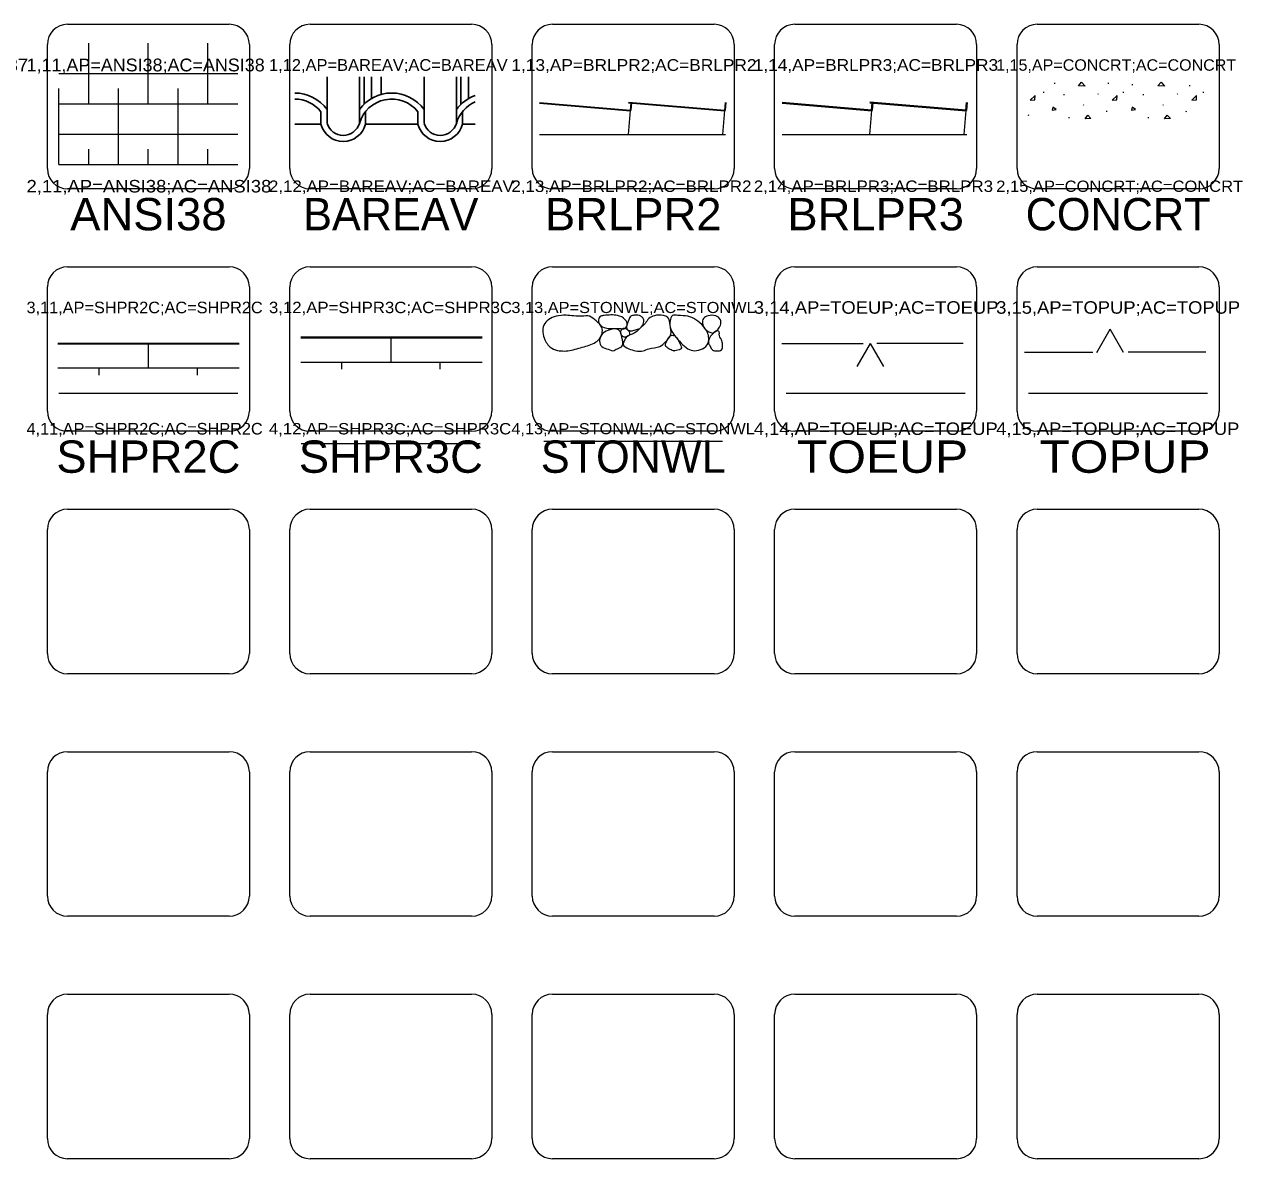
# Model space of a CAD drawing. Extents: x 95935 to 95946.4, y 95971.2 to 95974.7.
# Drawn here: x 95941.029 to 95944.034, y 95971.925 to 95974.732 of the extents above; entities that cross this region are included whole.
import ezdxf
from ezdxf.enums import TextEntityAlignment as Align

# ---------------------------------------------------------------- set-up
doc = ezdxf.new("R2010")
doc.units = 0
doc.header["$LTSCALE"] = 0.032
for name, color, linetype, lineweight in [('1', 7, 'Continuous', 13), ('25', 7, 'Continuous', 13), ('6', 7, 'Continuous', 13), ('63', 7, 'Continuous', 13)]:
    doc.layers.add(name, color=color, linetype=linetype, lineweight=lineweight)
doc.layers.add('20', color=7, linetype='Continuous')

msp = doc.modelspace()

# ---------------------------------------------------------------- linework, layer by layer
at = {"layer": '1'}
for p, q in [((95941.1357, 95974.7318), (95941.5357, 95974.7318)), ((95941.7357, 95974.7318), (95942.1357, 95974.7318)), ((95942.3357, 95974.7318), (95942.7357, 95974.7318)), ((95942.9357, 95974.7318), (95943.3357, 95974.7318)), ((95943.5357, 95974.7318), (95943.9357, 95974.7318)), ((95941.0857, 95974.3747), (95941.0857, 95974.6818)), ((95941.5857, 95974.6818), (95941.5857, 95974.3747)), ((95941.6857, 95974.3747), (95941.6857, 95974.6818)), ((95942.1857, 95974.6818), (95942.1857, 95974.3747)), ((95942.2857, 95974.3747), (95942.2857, 95974.6818)), ((95942.7857, 95974.6818), (95942.7857, 95974.3747)), ((95942.8857, 95974.3747), (95942.8857, 95974.6818)), ((95943.3857, 95974.6818), (95943.3857, 95974.3747)), ((95943.4857, 95974.3747), (95943.4857, 95974.6818)), ((95943.9857, 95974.6818), (95943.9857, 95974.3747)), ((95941.5357, 95974.3247), (95941.1357, 95974.3247)), ((95942.1357, 95974.3247), (95941.7357, 95974.3247)), ((95942.7357, 95974.3247), (95942.3357, 95974.3247)), ((95943.3357, 95974.3247), (95942.9357, 95974.3247)), ((95943.9357, 95974.3247), (95943.5357, 95974.3247)), ((95941.1357, 95974.1318), (95941.5357, 95974.1318)), ((95941.7357, 95974.1318), (95942.1357, 95974.1318)), ((95942.3357, 95974.1318), (95942.7357, 95974.1318)), ((95942.9357, 95974.1318), (95943.3357, 95974.1318)), ((95943.5357, 95974.1318), (95943.9357, 95974.1318)), ((95941.0857, 95973.7747), (95941.0857, 95974.0818)), ((95941.5857, 95974.0818), (95941.5857, 95973.7747)), ((95941.6857, 95973.7747), (95941.6857, 95974.0818)), ((95942.1857, 95974.0818), (95942.1857, 95973.7747)), ((95942.2857, 95973.7747), (95942.2857, 95974.0818)), ((95942.7857, 95974.0818), (95942.7857, 95973.7747)), ((95942.8857, 95973.7747), (95942.8857, 95974.0818)), ((95943.3857, 95974.0818), (95943.3857, 95973.7747)), ((95943.4857, 95973.7747), (95943.4857, 95974.0818)), ((95943.9857, 95974.0818), (95943.9857, 95973.7747)), ((95941.5357, 95973.7247), (95941.1357, 95973.7247)), ((95942.1357, 95973.7247), (95941.7357, 95973.7247)), ((95942.7357, 95973.7247), (95942.3357, 95973.7247)), ((95943.3357, 95973.7247), (95942.9357, 95973.7247)), ((95943.9357, 95973.7247), (95943.5357, 95973.7247)), ((95941.1357, 95973.5318), (95941.5357, 95973.5318)), ((95941.7357, 95973.5318), (95942.1357, 95973.5318)), ((95942.3357, 95973.5318), (95942.7357, 95973.5318)), ((95942.9357, 95973.5318), (95943.3357, 95973.5318)), ((95943.5357, 95973.5318), (95943.9357, 95973.5318)), ((95941.0857, 95973.1747), (95941.0857, 95973.4818)), ((95941.5857, 95973.4818), (95941.5857, 95973.1747)), ((95941.6857, 95973.1747), (95941.6857, 95973.4818)), ((95942.1857, 95973.4818), (95942.1857, 95973.1747)), ((95942.2857, 95973.1747), (95942.2857, 95973.4818)), ((95942.7857, 95973.4818), (95942.7857, 95973.1747)), ((95942.8857, 95973.1747), (95942.8857, 95973.4818)), ((95943.3857, 95973.4818), (95943.3857, 95973.1747)), ((95943.4857, 95973.1747), (95943.4857, 95973.4818)), ((95943.9857, 95973.4818), (95943.9857, 95973.1747)), ((95941.5357, 95973.1247), (95941.1357, 95973.1247)), ((95942.1357, 95973.1247), (95941.7357, 95973.1247)), ((95942.7357, 95973.1247), (95942.3357, 95973.1247)), ((95943.3357, 95973.1247), (95942.9357, 95973.1247)), ((95943.9357, 95973.1247), (95943.5357, 95973.1247)), ((95941.1357, 95972.9318), (95941.5357, 95972.9318)), ((95941.7357, 95972.9318), (95942.1357, 95972.9318)), ((95942.3357, 95972.9318), (95942.7357, 95972.9318)), ((95942.9357, 95972.9318), (95943.3357, 95972.9318)), ((95943.5357, 95972.9318), (95943.9357, 95972.9318)), ((95941.0857, 95972.5747), (95941.0857, 95972.8818)), ((95941.5857, 95972.8818), (95941.5857, 95972.5747)), ((95941.6857, 95972.5747), (95941.6857, 95972.8818)), ((95942.1857, 95972.8818), (95942.1857, 95972.5747)), ((95942.2857, 95972.5747), (95942.2857, 95972.8818)), ((95942.7857, 95972.8818), (95942.7857, 95972.5747)), ((95942.8857, 95972.5747), (95942.8857, 95972.8818)), ((95943.3857, 95972.8818), (95943.3857, 95972.5747)), ((95943.4857, 95972.5747), (95943.4857, 95972.8818)), ((95943.9857, 95972.8818), (95943.9857, 95972.5747)), ((95941.5357, 95972.5247), (95941.1357, 95972.5247)), ((95942.1357, 95972.5247), (95941.7357, 95972.5247)), ((95942.7357, 95972.5247), (95942.3357, 95972.5247)), ((95943.3357, 95972.5247), (95942.9357, 95972.5247)), ((95943.9357, 95972.5247), (95943.5357, 95972.5247)), ((95941.1357, 95972.3318), (95941.5357, 95972.3318)), ((95941.7357, 95972.3318), (95942.1357, 95972.3318)), ((95942.3357, 95972.3318), (95942.7357, 95972.3318)), ((95942.9357, 95972.3318), (95943.3357, 95972.3318)), ((95943.5357, 95972.3318), (95943.9357, 95972.3318)), ((95941.0857, 95971.9747), (95941.0857, 95972.2818)), ((95941.5857, 95972.2818), (95941.5857, 95971.9747)), ((95941.6857, 95971.9747), (95941.6857, 95972.2818)), ((95942.1857, 95972.2818), (95942.1857, 95971.9747)), ((95942.2857, 95971.9747), (95942.2857, 95972.2818)), ((95942.7857, 95972.2818), (95942.7857, 95971.9747)), ((95942.8857, 95971.9747), (95942.8857, 95972.2818)), ((95943.3857, 95972.2818), (95943.3857, 95971.9747)), ((95943.4857, 95971.9747), (95943.4857, 95972.2818)), ((95943.9857, 95972.2818), (95943.9857, 95971.9747)), ((95941.5357, 95971.9247), (95941.1357, 95971.9247)), ((95942.1357, 95971.9247), (95941.7357, 95971.9247)), ((95942.7357, 95971.9247), (95942.3357, 95971.9247)), ((95943.3357, 95971.9247), (95942.9357, 95971.9247)), ((95943.9357, 95971.9247), (95943.5357, 95971.9247))]:
    msp.add_line(p, q, dxfattribs=at)
for centre, start, end in [((95941.1357, 95974.6818), 90, 180), ((95941.5357, 95974.6818), 0, 90), ((95941.7357, 95974.6818), 90, 180), ((95942.1357, 95974.6818), 0, 90), ((95942.3357, 95974.6818), 90, 180), ((95942.7357, 95974.6818), 0, 90), ((95942.9357, 95974.6818), 90, 180), ((95943.3357, 95974.6818), 0, 90), ((95943.5357, 95974.6818), 90, 180), ((95943.9357, 95974.6818), 0, 90), ((95941.1357, 95974.3747), 180, 270), ((95941.5357, 95974.3747), 270, 0), ((95941.7357, 95974.3747), 180, 270), ((95942.1357, 95974.3747), 270, 0), ((95942.3357, 95974.3747), 180, 270), ((95942.7357, 95974.3747), 270, 0), ((95942.9357, 95974.3747), 180, 270), ((95943.3357, 95974.3747), 270, 0), ((95943.5357, 95974.3747), 180, 270), ((95943.9357, 95974.3747), 270, 0), ((95941.1357, 95974.0818), 90, 180), ((95941.5357, 95974.0818), 0, 90), ((95941.7357, 95974.0818), 90, 180), ((95942.1357, 95974.0818), 0, 90), ((95942.3357, 95974.0818), 90, 180), ((95942.7357, 95974.0818), 0, 90), ((95942.9357, 95974.0818), 90, 180), ((95943.3357, 95974.0818), 0, 90), ((95943.5357, 95974.0818), 90, 180), ((95943.9357, 95974.0818), 0, 90), ((95941.1357, 95973.7747), 180, 270), ((95941.5357, 95973.7747), 270, 0), ((95941.7357, 95973.7747), 180, 270), ((95942.1357, 95973.7747), 270, 0), ((95942.3357, 95973.7747), 180, 270), ((95942.7357, 95973.7747), 270, 0), ((95942.9357, 95973.7747), 180, 270), ((95943.3357, 95973.7747), 270, 0), ((95943.5357, 95973.7747), 180, 270), ((95943.9357, 95973.7747), 270, 0), ((95941.1357, 95973.4818), 90, 180), ((95941.5357, 95973.4818), 0, 90), ((95941.7357, 95973.4818), 90, 180), ((95942.1357, 95973.4818), 0, 90), ((95942.3357, 95973.4818), 90, 180), ((95942.7357, 95973.4818), 0, 90), ((95942.9357, 95973.4818), 90, 180), ((95943.3357, 95973.4818), 0, 90), ((95943.5357, 95973.4818), 90, 180), ((95943.9357, 95973.4818), 0, 90), ((95941.1357, 95973.1747), 180, 270), ((95941.5357, 95973.1747), 270, 0), ((95941.7357, 95973.1747), 180, 270), ((95942.1357, 95973.1747), 270, 0), ((95942.3357, 95973.1747), 180, 270), ((95942.7357, 95973.1747), 270, 0), ((95942.9357, 95973.1747), 180, 270), ((95943.3357, 95973.1747), 270, 0), ((95943.5357, 95973.1747), 180, 270), ((95943.9357, 95973.1747), 270, 0), ((95941.1357, 95972.8818), 90, 180), ((95941.5357, 95972.8818), 0, 90), ((95941.7357, 95972.8818), 90, 180), ((95942.1357, 95972.8818), 0, 90), ((95942.3357, 95972.8818), 90, 180), ((95942.7357, 95972.8818), 0, 90), ((95942.9357, 95972.8818), 90, 180), ((95943.3357, 95972.8818), 0, 90), ((95943.5357, 95972.8818), 90, 180), ((95943.9357, 95972.8818), 0, 90), ((95941.1357, 95972.5747), 180, 270), ((95941.5357, 95972.5747), 270, 0), ((95941.7357, 95972.5747), 180, 270), ((95942.1357, 95972.5747), 270, 0), ((95942.3357, 95972.5747), 180, 270), ((95942.7357, 95972.5747), 270, 0), ((95942.9357, 95972.5747), 180, 270), ((95943.3357, 95972.5747), 270, 0), ((95943.5357, 95972.5747), 180, 270), ((95943.9357, 95972.5747), 270, 0), ((95941.1357, 95972.2818), 90, 180), ((95941.5357, 95972.2818), 0, 90), ((95941.7357, 95972.2818), 90, 180), ((95942.1357, 95972.2818), 0, 90), ((95942.3357, 95972.2818), 90, 180), ((95942.7357, 95972.2818), 0, 90), ((95942.9357, 95972.2818), 90, 180), ((95943.3357, 95972.2818), 0, 90), ((95943.5357, 95972.2818), 90, 180), ((95943.9357, 95972.2818), 0, 90), ((95941.1357, 95971.9747), 180, 270), ((95941.5357, 95971.9747), 270, 0), ((95941.7357, 95971.9747), 180, 270), ((95942.1357, 95971.9747), 270, 0), ((95942.3357, 95971.9747), 180, 270), ((95942.7357, 95971.9747), 270, 0), ((95942.9357, 95971.9747), 180, 270), ((95943.3357, 95971.9747), 270, 0), ((95943.5357, 95971.9747), 180, 270), ((95943.9357, 95971.9747), 270, 0)]:
    msp.add_arc(centre, 0.05, start, end, dxfattribs=at)
at = {"layer": '25'}
for p, q in [((95941.5569, 95973.8178), (95941.1141, 95973.8178)), ((95943.3569, 95973.8178), (95942.9141, 95973.8178)), ((95943.9569, 95973.8178), (95943.5141, 95973.8178)), ((95942.1569, 95973.6934), (95941.7141, 95973.6934)), ((95942.7569, 95973.6996), (95942.3141, 95973.6996))]:
    msp.add_line(p, q, dxfattribs=at)
at = {"layer": '6'}
for p, q in [((95941.1879, 95974.5352), (95941.1879, 95974.6852)), ((95941.3355, 95974.5352), (95941.3355, 95974.6852)), ((95941.4831, 95974.5352), (95941.4831, 95974.6852)), ((95941.1141, 95974.6102), (95941.5569, 95974.6102)), ((95941.1141, 95974.3852), (95941.1141, 95974.5727)), ((95941.2617, 95974.3852), (95941.2617, 95974.5727)), ((95941.4093, 95974.3852), (95941.4093, 95974.5727)), ((95943.5521, 95974.562), (95943.5521, 95974.5643)), ((95943.579, 95974.5847), (95943.579, 95974.5872)), ((95943.7122, 95974.5847), (95943.7122, 95974.5872)), ((95943.7488, 95974.562), (95943.7488, 95974.5643)), ((95943.7714, 95974.581), (95943.7714, 95974.5834)), ((95943.9137, 95974.5789), (95943.9137, 95974.5814)), ((95943.9468, 95974.562), (95943.9468, 95974.5643)), ((95941.1141, 95974.5352), (95941.5569, 95974.5352)), ((95943.6021, 95974.5565), (95943.6021, 95974.559)), ((95943.687, 95974.5583), (95943.6863, 95974.56)), ((95943.7987, 95974.5565), (95943.7987, 95974.559)), ((95943.8836, 95974.5583), (95943.8828, 95974.56)), ((95942.5242, 95974.4591), (95942.5291, 95974.5187)), ((95942.7576, 95974.4591), (95942.7625, 95974.5187)), ((95943.1214, 95974.4591), (95943.1263, 95974.5187)), ((95943.3548, 95974.4591), (95943.3597, 95974.5187)), ((95943.5141, 95974.5062), (95943.5147, 95974.5087)), ((95943.6502, 95974.5316), (95943.6512, 95974.5336)), ((95943.7077, 95974.5149), (95943.7082, 95974.5175)), ((95943.8469, 95974.5316), (95943.8478, 95974.5336)), ((95943.9044, 95974.5149), (95943.9047, 95974.5175)), ((95943.6143, 95974.4998), (95943.6145, 95974.5018)), ((95943.811, 95974.4998), (95943.811, 95974.5018)), ((95941.1141, 95974.4602), (95941.5569, 95974.4602)), ((95942.3034, 95974.4591), (95942.5308, 95974.4591)), ((95942.5242, 95974.4591), (95942.7642, 95974.4591)), ((95942.9042, 95974.4591), (95943.128, 95974.4591)), ((95943.1214, 95974.4591), (95943.3614, 95974.4591)), ((95941.1879, 95974.3852), (95941.1879, 95974.4227)), ((95941.3355, 95974.3852), (95941.3355, 95974.4227)), ((95941.4831, 95974.3852), (95941.4831, 95974.4227)), ((95941.1141, 95974.3852), (95941.5569, 95974.3852)), ((95943.6833, 95973.92), (95943.7161, 95973.977)), ((95943.749, 95973.92), (95943.7161, 95973.977)), ((95941.3348, 95973.9421), (95941.3348, 95973.8814)), ((95941.3348, 95973.9421), (95941.3348, 95973.8814)), ((95941.9355, 95973.9565), (95941.9355, 95973.8958)), ((95941.9355, 95973.9565), (95941.9355, 95973.8958)), ((95942.9034, 95973.9418), (95943.1049, 95973.9418)), ((95943.0899, 95973.8849), (95943.1227, 95973.9418)), ((95943.1556, 95973.8849), (95943.1227, 95973.9418)), ((95943.3521, 95973.9418), (95943.1383, 95973.9418)), ((95943.5041, 95973.9201), (95943.6734, 95973.9201)), ((95943.9528, 95973.9201), (95943.7606, 95973.9201)), ((95941.1118, 95973.8814), (95941.3348, 95973.8814)), ((95941.2133, 95973.8814), (95941.2133, 95973.8639)), ((95941.3348, 95973.8814), (95941.5605, 95973.8814)), ((95941.4563, 95973.8814), (95941.4563, 95973.8639)), ((95941.7127, 95973.8958), (95941.9355, 95973.8958)), ((95941.814, 95973.8958), (95941.814, 95973.8783)), ((95941.9355, 95973.8958), (95942.1614, 95973.8958)), ((95942.057, 95973.8958), (95942.057, 95973.8783))]:
    msp.add_line(p, q, dxfattribs=at)
at = {"layer": '6', "lineweight": 25}
for p, q in [((95941.7779, 95974.4868), (95941.7779, 95974.6018)), ((95941.8579, 95974.4868), (95941.8579, 95974.6018)), ((95941.8694, 95974.534), (95941.8694, 95974.6018)), ((95941.8879, 95974.5481), (95941.8879, 95974.6018)), ((95941.9115, 95974.5582), (95941.9115, 95974.6018)), ((95942.0179, 95974.4868), (95942.0179, 95974.6018)), ((95942.0979, 95974.4868), (95942.0979, 95974.6018)), ((95942.1094, 95974.534), (95942.1094, 95974.6018)), ((95942.1279, 95974.5481), (95942.1279, 95974.6018)), ((95941.7629, 95974.4848), (95941.7629, 95974.5156)), ((95941.8729, 95974.4848), (95941.8729, 95974.5156)), ((95942.0029, 95974.4848), (95942.0029, 95974.5156)), ((95942.1129, 95974.4848), (95942.1129, 95974.5156)), ((95941.7629, 95974.4848), (95941.6979, 95974.4848)), ((95942.0029, 95974.4848), (95941.8729, 95974.4848)), ((95942.1448, 95974.4848), (95942.1129, 95974.4848))]:
    msp.add_line(p, q, dxfattribs=at)
at = {"layer": '6', "lineweight": 35}
for p, q in [((95942.3034, 95974.5375), (95942.5291, 95974.5187)), ((95942.5242, 95974.5385), (95942.7625, 95974.5187)), ((95942.5308, 95974.5385), (95942.5291, 95974.5187)), ((95942.7642, 95974.5385), (95942.7625, 95974.5187)), ((95941.1118, 95973.9421), (95941.3348, 95973.9421)), ((95941.3348, 95973.9421), (95941.5605, 95973.9421))]:
    msp.add_line(p, q, dxfattribs=at)
at = {"layer": '6', "lineweight": 40}
for p, q in [((95942.9042, 95974.5372), (95943.1263, 95974.5187)), ((95943.1214, 95974.5385), (95943.3597, 95974.5187)), ((95943.128, 95974.5385), (95943.1263, 95974.5187)), ((95943.3614, 95974.5385), (95943.3597, 95974.5187)), ((95941.7127, 95973.9565), (95941.9355, 95973.9565)), ((95941.9355, 95973.9565), (95942.1614, 95973.9565))]:
    msp.add_line(p, q, dxfattribs=at)
at = {"layer": '6'}
for points in [[(95943.6377, 95974.5798), (95943.6454, 95974.5882), (95943.6542, 95974.5788)], [(95943.8342, 95974.5798), (95943.8422, 95974.5882), (95943.8507, 95974.5788)], [(95943.5295, 95974.5446), (95943.5301, 95974.5558), (95943.5179, 95974.5439)], [(95943.7328, 95974.5446), (95943.7336, 95974.5558), (95943.7214, 95974.5439)], [(95943.9296, 95974.5446), (95943.9301, 95974.5558), (95943.918, 95974.5439)], [(95943.5727, 95974.5195), (95943.5827, 95974.5207), (95943.5742, 95974.5264)], [(95943.6544, 95974.4981), (95943.6609, 95974.507), (95943.6686, 95974.4985)], [(95943.7693, 95974.5195), (95943.7792, 95974.5207), (95943.7707, 95974.5264)], [(95943.8509, 95974.4981), (95943.8576, 95974.507), (95943.8652, 95974.4985)]]:
    msp.add_lwpolyline(points, close=True, dxfattribs=at)
at = {"layer": '6', "lineweight": 25}
for centre, radius, start, end in [((95941.6979, 95974.4634), 0.0983, 35.5548, 90), ((95941.6979, 95974.4634), 0.0833, 38.7394, 90), ((95941.9379, 95974.4634), 0.0983, 35.5548, 144.4452), ((95941.9379, 95974.4634), 0.0833, 38.7394, 163.7398), ((95942.1779, 95974.4634), 0.0983, 109.6705, 144.4452), ((95942.1779, 95974.4634), 0.0833, 113.4032, 163.7398), ((95941.8179, 95974.4984), 0.0567, 193.9306, 346.0694), ((95941.8179, 95974.4984), 0.0417, 196.2602, 343.7398), ((95942.0579, 95974.4984), 0.0567, 193.9306, 346.0694), ((95942.0579, 95974.4984), 0.0417, 196.2602, 343.7398)]:
    msp.add_arc(centre, radius, start, end, dxfattribs=at)
at = {"layer": '6'}
for points in [[(95942.3527, 95973.9238), (95942.3345, 95973.9301), (95942.317, 95973.9511), (95942.3144, 95973.9874), (95942.3446, 95974.0093), (95942.3693, 95974.0119), (95942.4082, 95974.0093), (95942.4275, 95974.0093), (95942.4441, 95973.998), (95942.458, 95973.9814), (95942.4519, 95973.9532), (95942.4387, 95973.9428), (95942.4053, 95973.9316), (95942.3693, 95973.9235), (95942.3527, 95973.9238)], [(95942.4775, 95973.9788), (95942.4634, 95973.9814), (95942.4513, 95973.9909), (95942.4496, 95974.0009), (95942.4554, 95974.0093), (95942.4637, 95974.0113), (95942.4965, 95974.0113), (95942.5161, 95974.0009), (95942.5204, 95973.9877), (95942.5144, 95973.9791), (95942.5051, 95973.9788), (95942.4775, 95973.9788)], [(95942.5411, 95973.9235), (95942.5244, 95973.929), (95942.5106, 95973.9399), (95942.5132, 95973.9483), (95942.5192, 95973.9583), (95942.5382, 95973.9675), (95942.552, 95973.9788), (95942.5659, 95973.9926), (95942.5742, 95974.0035), (95942.5883, 95974.0107), (95942.6102, 95974.011), (95942.6214, 95974.0064), (95942.6269, 95973.9871), (95942.6289, 95973.9652), (95942.6153, 95973.9457), (95942.6018, 95973.9345), (95942.5742, 95973.929), (95942.5604, 95973.9235), (95942.5411, 95973.9235)], [(95942.552, 95973.9788), (95942.5411, 95973.9759), (95942.5299, 95973.9733), (95942.5215, 95973.9759), (95942.519, 95973.9814), (95942.5215, 95973.9926), (95942.5244, 95974.0009), (95942.5299, 95974.0093), (95942.5382, 95974.0119), (95942.5549, 95974.0093), (95942.5604, 95974.0035), (95942.5604, 95973.9897), (95942.552, 95973.9788)], [(95942.6876, 95973.9235), (95942.6712, 95973.929), (95942.6545, 95973.9428), (95942.6378, 95973.9621), (95942.6271, 95973.9825), (95942.6269, 95973.998), (95942.6329, 95974.011), (95942.6464, 95974.0116), (95942.6712, 95974.0093), (95942.6904, 95974.0009), (95942.7097, 95973.9842), (95942.7224, 95973.9592), (95942.7209, 95973.9428), (95942.7071, 95973.929), (95942.6876, 95973.9235)], [(95942.7319, 95973.9675), (95942.7152, 95973.9759), (95942.7071, 95973.9926), (95942.7097, 95974.0035), (95942.7212, 95974.0104), (95942.7399, 95974.0104), (95942.7514, 95974.0009), (95942.7514, 95973.9874), (95942.7373, 95973.9704), (95942.7319, 95973.9675)], [(95942.4856, 95973.9235), (95942.4692, 95973.929), (95942.4554, 95973.9373), (95942.4525, 95973.9511), (95942.4608, 95973.9675), (95942.4778, 95973.9759), (95942.4994, 95973.9756), (95942.5077, 95973.9566), (95942.5086, 95973.9359), (95942.4968, 95973.929), (95942.4856, 95973.9235)], [(95942.5192, 95973.9583), (95942.5106, 95973.9595), (95942.5051, 95973.965), (95942.5051, 95973.9733), (95942.5106, 95973.9788), (95942.5215, 95973.9759), (95942.5273, 95973.965), (95942.5192, 95973.9583)], [(95942.7569, 95973.9316), (95942.754, 95973.9261), (95942.7431, 95973.9235), (95942.7319, 95973.9261), (95942.7264, 95973.9345), (95942.7224, 95973.9428), (95942.7235, 95973.9537), (95942.7319, 95973.965), (95942.7373, 95973.9704), (95942.7431, 95973.9733), (95942.7486, 95973.9704), (95942.7486, 95973.965), (95942.754, 95973.9511), (95942.7569, 95973.9399), (95942.7569, 95973.9316)], [(95942.6352, 95973.9235), (95942.624, 95973.929), (95942.6156, 95973.9373), (95942.6188, 95973.948), (95942.6297, 95973.9618), (95942.6352, 95973.9621), (95942.6456, 95973.9532), (95942.6516, 95973.9399), (95942.6545, 95973.929), (95942.6352, 95973.9235), (95942.6378, 95973.9235)]]:
    msp.add_spline(points, degree=3, dxfattribs=at)

# ---------------------------------------------------------------- texts
at = {"layer": '20'}
for s, width, p in [('ANSI38', 1.05, (95941.3357, 95974.222)), ('BRLPR2', 1.05, (95942.5357, 95974.222)), ('BRLPR3', 1.05, (95943.1357, 95974.222)), ('SHPR2C', 1.05, (95941.3357, 95973.622)), ('SHPR3C', 1.05, (95941.9358, 95973.622)), (' TOEUP', 1.15, (95943.1358, 95973.622)), (' TOPUP', 1.15, (95943.7358, 95973.622))]:
    msp.add_text(s, height=0.08, dxfattribs=dict(at, width=width)).set_placement(p, align=Align.CENTER)
for s, p in [('BAREAV', (95941.9357, 95974.222)), ('CONCRT', (95943.7358, 95974.222)), ('STONWL', (95942.5358, 95973.622))]:
    msp.add_text(s, height=0.08, dxfattribs=at).set_placement(p, align=Align.CENTER)
at = {"layer": '63'}
for s, height, width, p in [('1,10,AP=ANSI37;AC=ANSI37', 0.0309, 1.1, (95940.4341, 95974.6156)), ('1,11,AP=ANSI38;AC=ANSI38', 0.0316, 1.05, (95941.0341, 95974.6153)), ('1,12,AP=BAREAV;AC=BAREAV', 0.029, 1.05, (95941.6341, 95974.6166)), ('1,13,AP=BRLPR2;AC=BRLPR2', 0.0291, 1.1, (95942.2341, 95974.6165)), ('1,14,AP=BRLPR3;AC=BRLPR3', 0.029, 1.1, (95942.8341, 95974.6166)), ('1,15,AP=CONCRT;AC=CONCRT', 0.0283, 1.05, (95943.4341, 95974.6169)), ('2,11,AP=ANSI38;AC=ANSI38', 0.031, 1.1, (95941.0341, 95974.3156)), ('2,12,AP=BAREAV;AC=BAREAV', 0.0284, 1.1, (95941.6341, 95974.3169)), ('2,13,AP=BRLPR2;AC=BRLPR2', 0.0285, 1.1, (95942.2341, 95974.3168)), ('2,14,AP=BRLPR3;AC=BRLPR3', 0.0284, 1.1, (95942.8341, 95974.3169)), ('2,15,AP=CONCRT;AC=CONCRT', 0.0278, 1.1, (95943.4341, 95974.3172)), ('3,11,AP=SHPR2C;AC=SHPR2C', 0.0287, 1.05, (95941.0341, 95974.0167)), ('3,12,AP=SHPR3C;AC=SHPR3C', 0.0282, 1.1, (95941.6341, 95974.017)), ('3,13,AP=STONWL;AC=STONWL', 0.0275, 1.1, (95942.2341, 95974.0173)), ('3,14,AP=TOEUP;AC=TOEUP', 0.031, 1.1, (95942.8341, 95974.0156)), ('3,15,AP=TOPUP;AC=TOPUP', 0.0309, 1.1, (95943.4341, 95974.0156)), ('4,11,AP=SHPR2C;AC=SHPR2C', 0.0287, 1.05, (95941.0341, 95973.7167)), ('4,12,AP=SHPR3C;AC=SHPR3C', 0.0281, 1.1, (95941.6341, 95973.717)), ('4,13,AP=STONWL;AC=STONWL', 0.0274, 1.1, (95942.2341, 95973.7174)), ('4,14,AP=TOEUP;AC=TOEUP', 0.0309, 1.1, (95942.8341, 95973.7156)), ('4,15,AP=TOPUP;AC=TOPUP', 0.0308, 1.1, (95943.4341, 95973.7157))]:
    msp.add_text(s, height=height, dxfattribs=dict(at, width=width)).set_placement(p)

doc.saveas('drawing.dxf')
